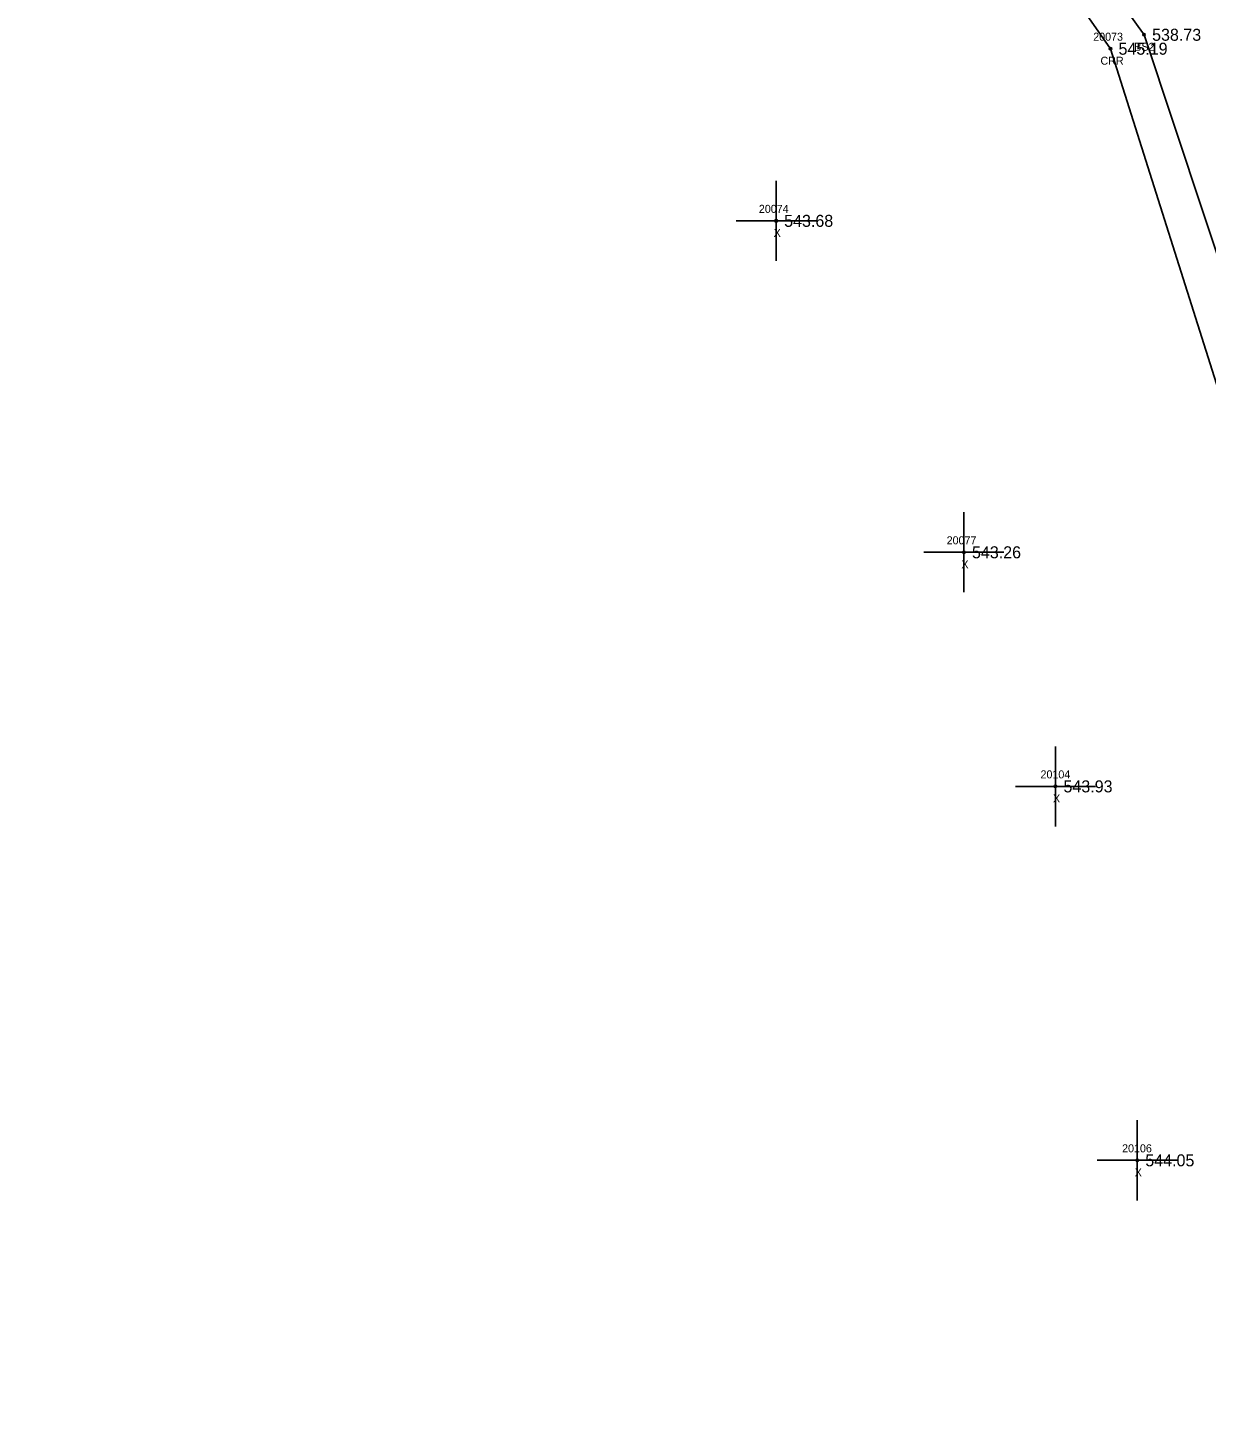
# Model space of a CAD drawing. Extents: x 1540443 to 1541844, y 887157 to 888162.
# Drawn here: x 1541137.7 to 1541285, y 887172.2 to 887345.9 of the extents above; entities that cross this region are included whole.
import ezdxf

# ---------------------------------------------------------------- set-up
doc = ezdxf.new("R2010")
doc.units = 0
for name, color, linetype in [('RD_DTM_BkLn2', 7, 'Continuous'), ('RD_DTM_BkLn_txCode', 7, 'Continuous'), ('RD_EX_H2O', 7, 'Continuous'), ('RD_EX_H2O_txCode', 7, 'Continuous'), ('RD_EX_Misc', 7, 'Continuous'), ('RD_EX_Misc_txCode', 7, 'Continuous'), ('RD_EX_TX_H2O_ELEV', 7, 'Continuous'), ('RD_EX_TX_Misc_ELEV', 7, 'Continuous'), ('RD_SMD_Locator', 7, 'Continuous')]:
    doc.layers.add(name, color=color, linetype=linetype)

msp = doc.modelspace()

# ---------------------------------------------------------------- linework, layer by layer
at = {"layer": 'RD_DTM_BkLn2'}
msp.add_lwpolyline([(1541146.1, 887665.49), (1541150.74, 887637.01), (1541158.36, 887596.65), (1541173.42, 887559.93), (1541207.19, 887515.92), (1541227.14, 887479.24), (1541238.45, 887421.16), (1541256.87, 887373.46), (1541277.28, 887344.99), (1541292.28, 887299.84), (1541309.01, 887259.64), (1541319.98, 887221.42), (1541339.02, 887172.82)], dxfattribs=at)
at = {"layer": 'RD_EX_H2O'}
msp.add_lwpolyline([(1541139.32, 887662.55), (1541137.72, 887649.7), (1541145.14, 887602.62), (1541162.15, 887562.57), (1541203.5, 887513.91), (1541216.11, 887476.29), (1541233.11, 887419.79), (1541253.41, 887371.38), (1541273.08, 887343.25), (1541287.88, 887296.49), (1541302.23, 887257.73), (1541317.42, 887219.54), (1541335.4, 887172.24)], dxfattribs=at)
at = {"layer": 'RD_EX_Misc'}
for p, q in [((1541231.28, 887316.74), (1541231.28, 887326.74)), ((1541226.28, 887321.74), (1541236.28, 887321.74)), ((1541254.76, 887275.32), (1541254.76, 887285.32)), ((1541249.76, 887280.32), (1541259.76, 887280.32)), ((1541266.2, 887246.07), (1541266.2, 887256.07)), ((1541261.2, 887251.07), (1541271.2, 887251.07)), ((1541276.43, 887199.34), (1541276.43, 887209.34)), ((1541271.43, 887204.34), (1541281.43, 887204.34))]:
    msp.add_line(p, q, dxfattribs=at)
at = {"layer": 'RD_SMD_Locator'}
for centre in [(1541277.28, 887344.99), (1541273.08, 887343.25), (1541231.28, 887321.74), (1541254.76, 887280.32), (1541266.2, 887251.07), (1541276.43, 887204.34)]:
    msp.add_circle(centre, 0.15, dxfattribs=at)

# ---------------------------------------------------------------- texts
at = {"layer": 'RD_DTM_BkLn_txCode'}
msp.add_text('BS2', height=1, dxfattribs=at).set_placement((1541276.05, 887342.99))
at = {"layer": 'RD_EX_H2O_txCode'}
for s, p in [('20073', (1541270.92, 887344.25)), ('CRR', (1541271.83, 887341.25))]:
    msp.add_text(s, height=1, dxfattribs=at).set_placement(p)
at = {"layer": 'RD_EX_Misc_txCode'}
for s, p in [('20074', (1541229.12, 887322.74)), ('X', (1541230.97, 887319.74)), ('20077', (1541252.6, 887281.32)), ('X', (1541254.44, 887278.32)), ('20104', (1541264.33, 887252.07)), ('X', (1541265.89, 887249.07)), ('20106', (1541274.53, 887205.34)), ('X', (1541276.11, 887202.34))]:
    msp.add_text(s, height=1, dxfattribs=at).set_placement(p)
at = {"layer": 'RD_EX_TX_H2O_ELEV'}
msp.add_text('545.19', height=1.5, dxfattribs=at).set_placement((1541274.08, 887342.5))
at = {"layer": 'RD_EX_TX_Misc_ELEV'}
for s, p in [('538.73', (1541278.28, 887344.24)), ('543.68', (1541232.28, 887320.99)), ('543.26', (1541255.76, 887279.57)), ('543.93', (1541267.2, 887250.32)), ('544.05', (1541277.43, 887203.59))]:
    msp.add_text(s, height=1.5, dxfattribs=at).set_placement(p)

doc.saveas('drawing.dxf')
